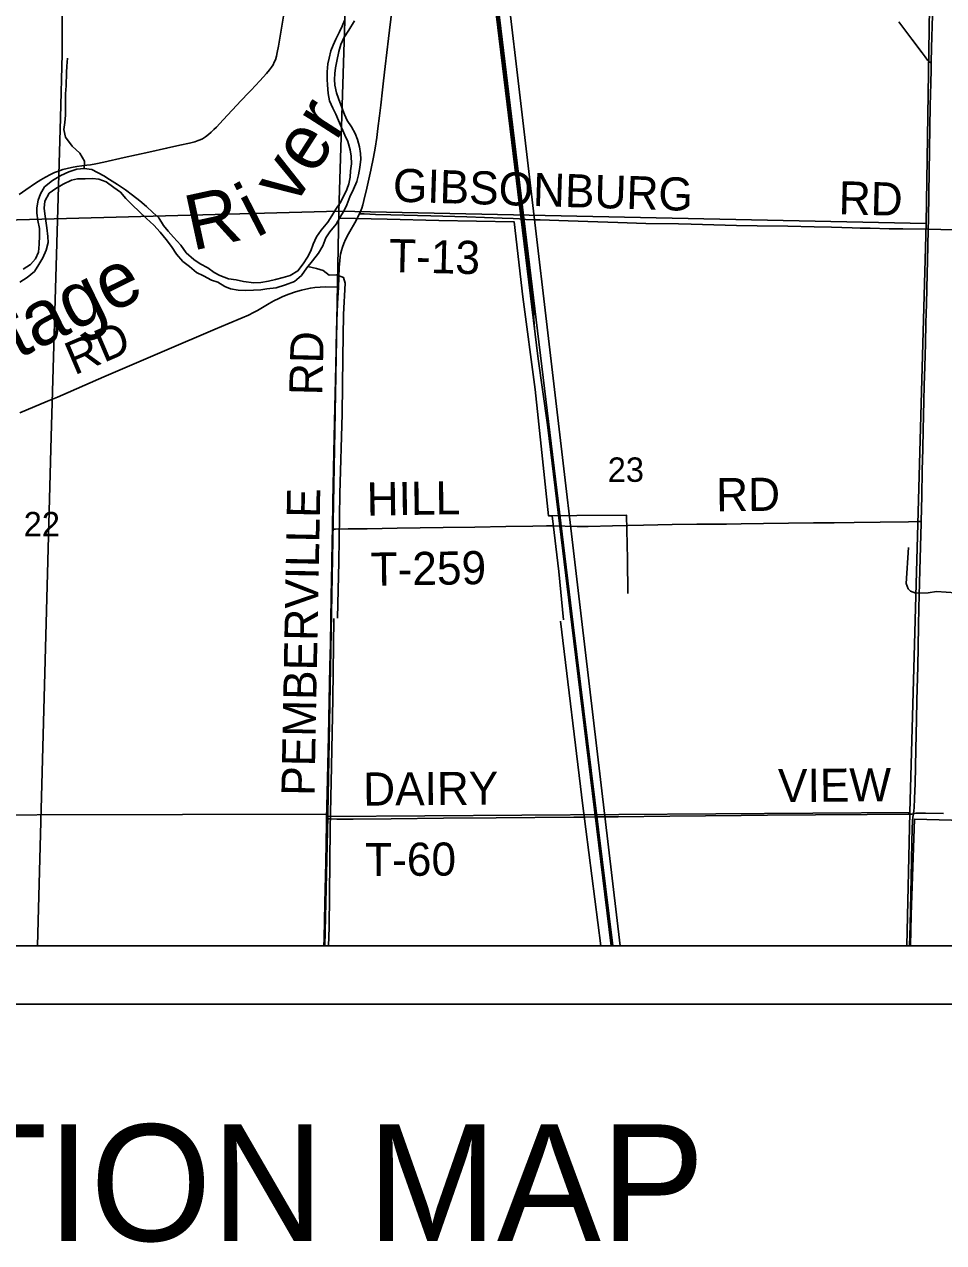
# Model space of a CAD drawing. Extents: x -8.3 to 42.1, y 0 to 22.
# Drawn here: x 5.28 to 6.858, y 13.591 to 15.682 of the extents above; entities that cross this region are included whole.
import ezdxf

# ---------------------------------------------------------------- set-up
doc = ezdxf.new("R2010")
doc.units = 0
for name, color, linetype in [('Default', 7, 'Continuous'), ('GM_X_County_Road', 7, 'Continuous'), ('GM_X_County_Road_Text', 7, 'Continuous'), ('GM_X_Major_River', 7, 'Continuous'), ('GM_X_Major_River_Text', 7, 'Continuous'), ('GM_X_Minor_River', 7, 'Continuous'), ('GM_X_Rail_Line', 7, 'Continuous'), ('GM_X_Section', 7, 'Continuous'), ('GM_X_Section_Text', 7, 'Continuous'), ('GM_X_Township_Road', 7, 'Continuous'), ('GM_X_Township_Road_Text', 7, 'Continuous'), ('SH_Cut_Line', 7, 'Continuous'), ('SH_Data', 7, 'Continuous'), ('SH_Text', 7, 'Continuous')]:
    doc.layers.add(name, color=color, linetype=linetype)

msp = doc.modelspace()

# ---------------------------------------------------------------- linework, layer by layer
at = {"layer": 'Default'}
for points in [[(4.7944, 14.1), (5.7957, 14.1), (5.8007, 14.322), (5.8007, 14.3261), (4.8014, 14.3239)], [(5.7957, 14.1), (6.7948, 14.1), (6.8001, 14.3291), (5.8007, 14.322)]]:
    msp.add_lwpolyline(points, close=True, dxfattribs=at)
at = {"layer": 'GM_X_County_Road'}
for points in [[(5.2707, 15.3896), (5.2822, 15.3976), (5.2989, 15.4089), (5.308, 15.4148), (5.316, 15.4195), (5.3242, 15.4239), (5.3312, 15.4271), (5.3384, 15.4299), (5.3457, 15.4323), (5.3532, 15.4344), (5.3607, 15.4361), (5.3699, 15.4376), (5.3868, 15.4397), (5.393, 15.4406), (5.4022, 15.4421), (5.416, 15.4449), (5.4508, 15.4531), (5.4933, 15.4624), (5.5237, 15.469), (5.5465, 15.474), (5.5632, 15.4778), (5.5722, 15.4801), (5.5782, 15.4821), (5.5812, 15.4833), (5.5854, 15.4853), (5.5908, 15.4886), (5.5958, 15.4924), (5.6006, 15.4965), (5.605, 15.5009), (5.6093, 15.5054), (5.621, 15.5179), (5.6518, 15.5508), (5.6647, 15.5643), (5.669, 15.5688), (5.6839, 15.5847), (5.6955, 15.5973), (5.7005, 15.6033), (5.7042, 15.6084), (5.7067, 15.6124), (5.7088, 15.6166), (5.7106, 15.621), (5.7125, 15.627), (5.7139, 15.6331), (5.7158, 15.6439), (5.7198, 15.6684), (5.7276, 15.7128)], [(5.8549, 15.3567), (5.8566, 15.3605), (5.8588, 15.3663), (5.8607, 15.3721), (5.8627, 15.3796), (5.8678, 15.4007), (5.8744, 15.4311), (5.879, 15.4539), (5.8818, 15.4692), (5.8847, 15.4876), (5.8867, 15.5029), (5.8893, 15.5245), (5.8916, 15.543), (5.8947, 15.5692), (5.8965, 15.5847), (5.8994, 15.6093), (5.9051, 15.6572), (5.9106, 15.705)], [(5.8188, 15.2308), (5.8204, 15.2641), (5.8212, 15.2765), (5.8218, 15.2828), (5.8225, 15.2874), (5.8239, 15.2935), (5.8258, 15.2995), (5.8281, 15.3054), (5.8313, 15.3125), (5.8364, 15.3222), (5.8492, 15.3452), (5.8534, 15.3535), (5.8549, 15.3567)], [(5.8085, 14.8151), (5.8091, 14.862), (5.8109, 14.9471), (5.8127, 15.0248), (5.8142, 15.0957), (5.8157, 15.1566), (5.8174, 15.2024), (5.8188, 15.2308)], [(5.7984, 14.3184), (5.7994, 14.3622), (5.8016, 14.4598), (5.8029, 14.5207), (5.8042, 14.5804), (5.8051, 14.619), (5.8066, 14.6997), (5.8076, 14.7563), (5.8082, 14.7967), (5.8085, 14.8151)], [(5.7939, 14.1), (5.7942, 14.113), (5.7953, 14.1733), (5.7971, 14.2441), (5.7982, 14.3094), (5.7984, 14.3184)]]:
    msp.add_lwpolyline(points, dxfattribs=at)
at = {"layer": 'GM_X_Major_River'}
for points in [[(5.8295, 15.6885), (5.8251, 15.6783), (5.8207, 15.6686), (5.8143, 15.6562), (5.8099, 15.6461), (5.8059, 15.6359), (5.8029, 15.6238), (5.8008, 15.614), (5.7993, 15.6), (5.7994, 15.5871), (5.7999, 15.5776), (5.801, 15.5632), (5.8034, 15.5502), (5.8091, 15.5379), (5.8142, 15.5275), (5.8192, 15.5168), (5.8299, 15.4914), (5.8348, 15.4803), (5.8388, 15.4665), (5.8406, 15.4554), (5.8412, 15.4423), (5.8398, 15.4305), (5.8391, 15.4192), (5.837, 15.4082), (5.8333, 15.3984), (5.8277, 15.386), (5.8221, 15.3752), (5.8147, 15.3647), (5.8076, 15.3528), (5.8005, 15.3419), (5.7892, 15.3285), (5.7811, 15.3172), (5.7757, 15.3046), (5.7716, 15.2929), (5.766, 15.282), (5.7586, 15.2704), (5.7492, 15.2585), (5.7361, 15.2505), (5.7239, 15.247), (5.7106, 15.2439), (5.6987, 15.2408), (5.6854, 15.2388), (5.6737, 15.2383), (5.6559, 15.2403), (5.6431, 15.2429), (5.6299, 15.2451), (5.6155, 15.2505), (5.6057, 15.2556), (5.5946, 15.2636), (5.5817, 15.2705), (5.5706, 15.2781), (5.5576, 15.2897), (5.5481, 15.3029), (5.5359, 15.3164), (5.5263, 15.3265), (5.5186, 15.3362), (5.5102, 15.3493), (5.5004, 15.3589), (5.4895, 15.3688), (5.478, 15.3786), (5.4654, 15.3887), (5.4535, 15.3978), (5.4393, 15.4068), (5.4255, 15.4155), (5.4158, 15.4218), (5.3956, 15.4326), (5.382, 15.4344), (5.3695, 15.4332), (5.3558, 15.4286), (5.342, 15.4221)], [(5.5126, 15.325), (5.5229, 15.3122), (5.5321, 15.3006), (5.5409, 15.2875), (5.5519, 15.2747), (5.5634, 15.2661), (5.5753, 15.2559), (5.5873, 15.2503), (5.6011, 15.2428), (5.612, 15.2391), (5.6239, 15.2316), (5.6337, 15.2279), (5.6469, 15.2253), (5.6586, 15.2247), (5.673, 15.2255), (5.6855, 15.2259), (5.6958, 15.2276), (5.7119, 15.2295), (5.7278, 15.2344), (5.7434, 15.2406), (5.7554, 15.2504), (5.7645, 15.2638), (5.7742, 15.2758), (5.7844, 15.2892), (5.7919, 15.3015), (5.7975, 15.315), (5.8042, 15.3255), (5.8152, 15.3389), (5.8207, 15.349), (5.8286, 15.3621), (5.8334, 15.3719), (5.8387, 15.3854), (5.8447, 15.3985), (5.8503, 15.4121), (5.8532, 15.4234), (5.8558, 15.4358), (5.8573, 15.4502), (5.8568, 15.4597), (5.8552, 15.4715), (5.8517, 15.4838), (5.8478, 15.4945), (5.8416, 15.5056), (5.834, 15.5168), (5.8293, 15.5268), (5.8229, 15.5433), (5.819, 15.5544), (5.8158, 15.5643), (5.8127, 15.5773), (5.8122, 15.5872), (5.8129, 15.597), (5.8139, 15.6069), (5.816, 15.6182), (5.8195, 15.6352), (5.8228, 15.6469), (5.828, 15.6582), (5.837, 15.6716), (5.8462, 15.6877)], [(5.2719, 15.239), (5.2842, 15.247), (5.297, 15.2577), (5.3045, 15.2693), (5.3112, 15.2809), (5.3172, 15.294), (5.3202, 15.3072), (5.3197, 15.3175), (5.3182, 15.3323), (5.3162, 15.3442), (5.3146, 15.3563), (5.3133, 15.3659), (5.3148, 15.3783), (5.3219, 15.3918), (5.3338, 15.3999), (5.3462, 15.4076), (5.3603, 15.4141), (5.371, 15.4165), (5.3842, 15.4165), (5.3968, 15.4173), (5.4077, 15.4159), (5.4201, 15.4111), (5.4331, 15.4017), (5.4446, 15.3934), (5.4538, 15.3829), (5.4649, 15.3717), (5.4893, 15.3483), (5.5016, 15.337), (5.5126, 15.325)], [(5.342, 15.4221), (5.3277, 15.4137), (5.3142, 15.4026), (5.3071, 15.3907), (5.3034, 15.3801), (5.3012, 15.3669), (5.301, 15.3574), (5.3026, 15.3452), (5.3053, 15.3315), (5.3057, 15.3186), (5.305, 15.3042), (5.3039, 15.2909), (5.2987, 15.2793), (5.2901, 15.2696), (5.2774, 15.2612)]]:
    msp.add_lwpolyline(points, dxfattribs=at)
at = {"layer": 'GM_X_Minor_River'}
for points in [[(5.382, 15.4344), (5.3827, 15.4469), (5.3747, 15.4608), (5.3614, 15.4725), (5.35, 15.4879), (5.3473, 15.5013), (5.3488, 15.5134), (5.3502, 15.5259), (5.3501, 15.5373), (5.3501, 15.5521), (5.3504, 15.5623), (5.3515, 15.5763), (5.352, 15.5991), (5.3527, 15.6101), (5.3534, 15.6237)], [(5.8207, 15.349), (5.9028, 15.3474), (5.9914, 15.3449), (6.1209, 15.3425), (6.1355, 15.2139), (6.1565, 15.0551), (6.1682, 14.947), (6.1795, 14.8382), (6.186, 14.8381), (6.2284, 14.8389), (6.3133, 14.8395), (6.3152, 14.764), (6.316, 14.7047)], [(5.7663, 15.2661), (5.7811, 15.2627), (5.7927, 15.2594), (5.8031, 15.2511), (5.8153, 15.252), (5.8277, 15.247), (5.8304, 15.2376)], [(5.8304, 15.2376), (5.8276, 15.1834), (5.8265, 15.1098), (5.8253, 15.0134), (5.8211, 14.8761), (5.8194, 14.7593), (5.817, 14.6626)], [(6.186, 14.8381), (6.1976, 14.7425), (6.2054, 14.6596)], [(6.9453, 14.7016), (6.8458, 14.7082), (6.8318, 14.7062), (6.8106, 14.7056), (6.8012, 14.7089), (6.7975, 14.7128), (6.7939, 14.7223), (6.7981, 14.7841)], [(5.811, 14.6622), (5.809, 14.524), (5.8071, 14.4082), (5.8048, 14.3015), (5.803, 14.1317), (5.8021, 14.1)], [(6.2004, 14.6574), (6.2387, 14.3405), (6.2694, 14.1)], [(7.0976, 14.3332), (7.0975, 14.3135), (6.9572, 14.3135), (6.808, 14.3174), (6.8025, 14.1535), (6.8011, 14.1)]]:
    msp.add_lwpolyline(points, dxfattribs=at)
at = {"layer": 'GM_X_Rail_Line'}
for p, q in [((6.1553, 15.1601), (6.1529, 15.1995)), ((6.1529, 15.1995), (6.1579, 15.18)), ((6.2364, 14.6613), (6.3024, 14.1))]:
    msp.add_line(p, q, dxfattribs=at)
for points in [[(6.2899, 14.1), (6.2222, 14.6512), (6.0176, 16.3351), (5.9781, 16.679), (5.9602, 16.8313), (5.9345, 17.0381), (5.9111, 17.2249), (5.9006, 17.3084), (5.8846, 17.4439), (5.8413, 17.6862), (5.7347, 18.3108), (5.559, 19.3267), (5.4294, 20.0826), (5.2883, 20.9)], [(5.9383, 17.037), (5.9498, 17.0314), (5.958, 17.0231), (6.2364, 14.6613)], [(5.3428, 16.9248), (5.3604, 16.689), (5.3556, 16.5985), (5.3541, 16.4612), (5.3493, 16.2965), (5.3382, 15.8766), (5.3398, 15.8056), (5.3447, 15.7232), (5.3447, 15.6312), (5.3415, 15.5213), (5.3256, 14.9739), (5.302, 14.1)], [(6.178, 14.9941), (6.1617, 15.1075), (6.0126, 16.3345), (5.9736, 16.679), (5.9639, 16.7758)], [(6.1529, 15.1995), (6.1528, 15.2014), (6.0151, 16.3348), (5.9835, 16.6131)], [(6.2874, 14.1), (6.2197, 14.6509), (6.178, 14.9941)]]:
    msp.add_lwpolyline(points, dxfattribs=at)
at = {"layer": 'GM_X_Section'}
for points in [[(4.8464, 16.3395), (5.8503, 16.3424), (5.8197, 15.3608), (4.8204, 15.3344)], [(5.8503, 16.3424), (6.8436, 16.3404), (6.8279, 15.3401), (5.8197, 15.3608)], [(5.8197, 15.3608), (5.8007, 14.3261), (4.8014, 14.3239), (4.8204, 15.3344)], [(6.8279, 15.3401), (6.8001, 14.3291), (5.8007, 14.322), (5.8007, 14.3261), (5.8197, 15.3608)]]:
    msp.add_lwpolyline(points, close=True, dxfattribs=at)
at = {"layer": 'GM_X_Township_Road'}
for points in [[(6.8368, 15.6155), (6.8368, 15.6166), (6.8376, 15.6415), (6.8388, 15.6974), (6.8404, 15.7595), (6.8425, 15.8668), (6.8433, 15.8963), (6.8455, 16.0066), (6.8478, 16.1449), (6.8489, 16.232), (6.8496, 16.2739), (6.85, 16.3019), (6.8503, 16.3361)], [(6.7812, 15.6861), (6.8037, 15.6564), (6.8213, 15.6326), (6.8262, 15.6257), (6.8305, 15.62), (6.8335, 15.6172), (6.8368, 15.6155)], [(6.8315, 15.33), (6.8319, 15.3462), (6.8326, 15.3913), (6.8338, 15.4659), (6.8344, 15.5047), (6.8352, 15.542), (6.8363, 15.5809), (6.8365, 15.6042), (6.8368, 15.6155)], [(5.8549, 15.3567), (5.8603, 15.3564), (5.8632, 15.3563), (5.8828, 15.3555), (5.9091, 15.3546), (5.9775, 15.3531), (6.0396, 15.3513), (6.1002, 15.3492), (6.1188, 15.3485), (6.1297, 15.348), (6.1343, 15.3475), (6.1405, 15.347), (6.1544, 15.3463), (6.1652, 15.3459), (6.2134, 15.3442), (6.2646, 15.3426), (6.2988, 15.3417), (6.3469, 15.3401), (6.4028, 15.339), (6.4246, 15.3385), (6.5023, 15.3366), (6.538, 15.3359), (6.5908, 15.335), (6.6359, 15.334), (6.6654, 15.3333), (6.7011, 15.3325), (6.715, 15.3321), (6.7321, 15.3317), (6.7647, 15.3309), (6.788, 15.3306), (6.8315, 15.33)], [(6.8195, 14.8285), (6.8205, 14.8723), (6.8214, 14.9159), (6.8222, 14.9531), (6.8231, 14.9858), (6.8244, 15.0355), (6.825, 15.0619), (6.8257, 15.0945), (6.8268, 15.1334), (6.8277, 15.1691), (6.8287, 15.2017), (6.8293, 15.2281), (6.8309, 15.3012), (6.8315, 15.33)], [(6.8315, 15.33), (6.8533, 15.3297), (6.8874, 15.3292)], [(5.2717, 15.0149), (5.3191, 15.0347), (5.3362, 15.0421), (5.3547, 15.0501), (5.3832, 15.0626), (5.416, 15.0768), (5.456, 15.0938), (5.5204, 15.1211), (5.6074, 15.1588), (5.6288, 15.1678), (5.6533, 15.1778), (5.6647, 15.1827), (5.6731, 15.1869), (5.68, 15.1907), (5.7, 15.2026), (5.7081, 15.2071), (5.7164, 15.2113), (5.7235, 15.2144), (5.7336, 15.2183), (5.7453, 15.2224), (5.7556, 15.2255), (5.7631, 15.2274), (5.7707, 15.2289), (5.7783, 15.23), (5.7876, 15.2307), (5.7968, 15.231), (5.8188, 15.2308)], [(5.8085, 14.8151), (5.8138, 14.8152), (5.8355, 14.8156), (5.8682, 14.8161), (5.9195, 14.8168), (5.9988, 14.818), (6.0533, 14.8188), (6.1062, 14.8199), (6.1528, 14.8206), (6.1762, 14.8208), (6.187, 14.8208), (6.2291, 14.8199), (6.2478, 14.82), (6.2897, 14.8209), (6.3425, 14.8224), (6.3922, 14.8235), (6.4341, 14.824), (6.459, 14.824), (6.4854, 14.8241), (6.5102, 14.8244), (6.5491, 14.8249), (6.6345, 14.8261), (6.6702, 14.8264), (6.7044, 14.8269), (6.7494, 14.8272), (6.7976, 14.8279), (6.8131, 14.8283), (6.8195, 14.8285)], [(6.8063, 14.3268), (6.8071, 14.3333), (6.8075, 14.3364), (6.8083, 14.3534), (6.809, 14.3782), (6.8102, 14.4373), (6.8114, 14.4886), (6.812, 14.5212), (6.8136, 14.5802), (6.8146, 14.6129), (6.8152, 14.6501), (6.8157, 14.6797), (6.8173, 14.7449), (6.8194, 14.8257), (6.8195, 14.8285)], [(5.7984, 14.3184), (5.8051, 14.3182), (5.816, 14.3179), (5.844, 14.3179), (5.9092, 14.3184), (5.9994, 14.3193), (6.0895, 14.3199), (6.2232, 14.3211), (6.2403, 14.3213), (6.2604, 14.3216), (6.2806, 14.3216), (6.2993, 14.3218), (6.3879, 14.3227), (6.5106, 14.3238), (6.5557, 14.3243), (6.6381, 14.3251), (6.7267, 14.3255), (6.7975, 14.3262), (6.803, 14.3261), (6.8063, 14.3268)], [(6.7996, 14.1), (6.8005, 14.136), (6.8022, 14.2168), (6.8035, 14.2774), (6.8042, 14.3008), (6.8049, 14.3148), (6.8055, 14.321), (6.8063, 14.3268)], [(6.8063, 14.3268), (6.8075, 14.3272), (6.8106, 14.3281), (6.8161, 14.328), (6.8271, 14.3279), (6.8582, 14.3272)], [(2.1, 14.1), (7.8013, 14.1)]]:
    msp.add_lwpolyline(points, dxfattribs=at)
at = {"layer": 'SH_Cut_Line'}
msp.add_lwpolyline([(2.1, 14.1), (7.8013, 14.1)], dxfattribs=at)
at = {"layer": 'SH_Data'}
for p, q in [((2.1, 14.1), (8.9, 14.1)), ((2, 14), (9, 14))]:
    msp.add_line(p, q, dxfattribs=at)

# ---------------------------------------------------------------- texts
at = {"layer": 'GM_X_County_Road_Text'}
for s, height, rotation, p in [('RD', 0.05682, 88.5163, (5.791, 15.0445)), ('PEMBERVILLE', 0.056818, 88.9073, (5.7777, 14.3572))]:
    msp.add_text(s, height=height, rotation=rotation, dxfattribs=at).set_placement(p)
at = {"layer": 'GM_X_Major_River_Text'}
for s, height, rotation, p in [('ver', 0.09476, 57.2835, (5.7424, 15.367)), ('i', 0.0948, 27.2833, (5.6774, 15.3146)), ('R', 0.0948, 12.2825, (5.5678, 15.2929)), ('Portage', 0.09475, 26.2292, (5.0913, 15.0198))]:
    msp.add_text(s, height=height, rotation=rotation, dxfattribs=at).set_placement(p)
at = {"layer": 'GM_X_Section_Text'}
for s, p in [('23', (6.2813, 14.8965)), ('22', (5.2784, 14.803))]:
    msp.add_text(s, height=0.04186, rotation=0, dxfattribs=at).set_placement(p)
at = {"layer": 'GM_X_Township_Road_Text'}
for s, rotation, p in [('GIBSONBURG', 358.2026, (5.9118, 15.3775)), ('RD', 358.5235, (6.6774, 15.3558)), ('T-13', 358.6013, (5.9052, 15.2566)), ('RD', 23.0637, (5.3654, 15.079)), ('HILL', 0.9008, (5.8678, 14.8385)), ('RD', 0.482, (6.4677, 14.846)), ('T-259', 0.8392, (5.8744, 14.7182)), ('VIEW', 0.5253, (6.5741, 14.3467)), ('DAIRY', 0.4338, (5.8615, 14.3408)), ('T-60', 0.3535, (5.8648, 14.2199))]:
    msp.add_text(s, height=0.05682, rotation=rotation, dxfattribs=at).set_placement(p)
at = {"layer": 'SH_Text'}
msp.add_text('LOCATION MAP', height=0.2, dxfattribs=at).set_placement((4.4269, 13.5938))

doc.saveas('drawing.dxf')
